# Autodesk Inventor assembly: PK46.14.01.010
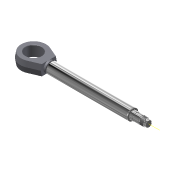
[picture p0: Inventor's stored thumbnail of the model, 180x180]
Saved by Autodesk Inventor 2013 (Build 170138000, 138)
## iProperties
Shininess: 64.0
Length Units: 11269
Angle Units: 11279
Time Units: 11290
Mass Units: 11283
Length Display Precision: 3
Angle Display Precision: 2
Compacted: True
Created: 2004-11
Part Number: PK46.14.01.010
Document SubType Name: Assembly
Designer: ELarisa
Manufacturer: Standard
Standards Organization: Custom
Density: 0.0
Volumn: 0.0
Area: 0.0
PropertySet Name: Model Information
Control State: 0
Master: False
Checked Out: False
Checked Out Date: 2008-10-15
Last Check In Date: 2008-10-15
Author: ELarisa
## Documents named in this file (3)
- C:\Product Design Suite 2013\Data\Assemblies\PK46.14.01.010.iam
- C:\Product Design Suite 2013\Data\Parts\PK46.14.01.001.ipt
- C:\Product Design Suite 2013\Data\Parts\PK46.14.01.008.ipt
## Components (2 placed, 2 different names)
1. PK46.14.01.001:1 — Insert:1, Angle:1
2. PK46.14.01.008:1 — Insert:1, Angle:1
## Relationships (2: Insert 1, Angle 1)
- Insert:1: PK46.14.01.001:1 ↔ PK46.14.01.008:1
- Angle:1: PK46.14.01.001:1 ↔ PK46.14.01.008:1
